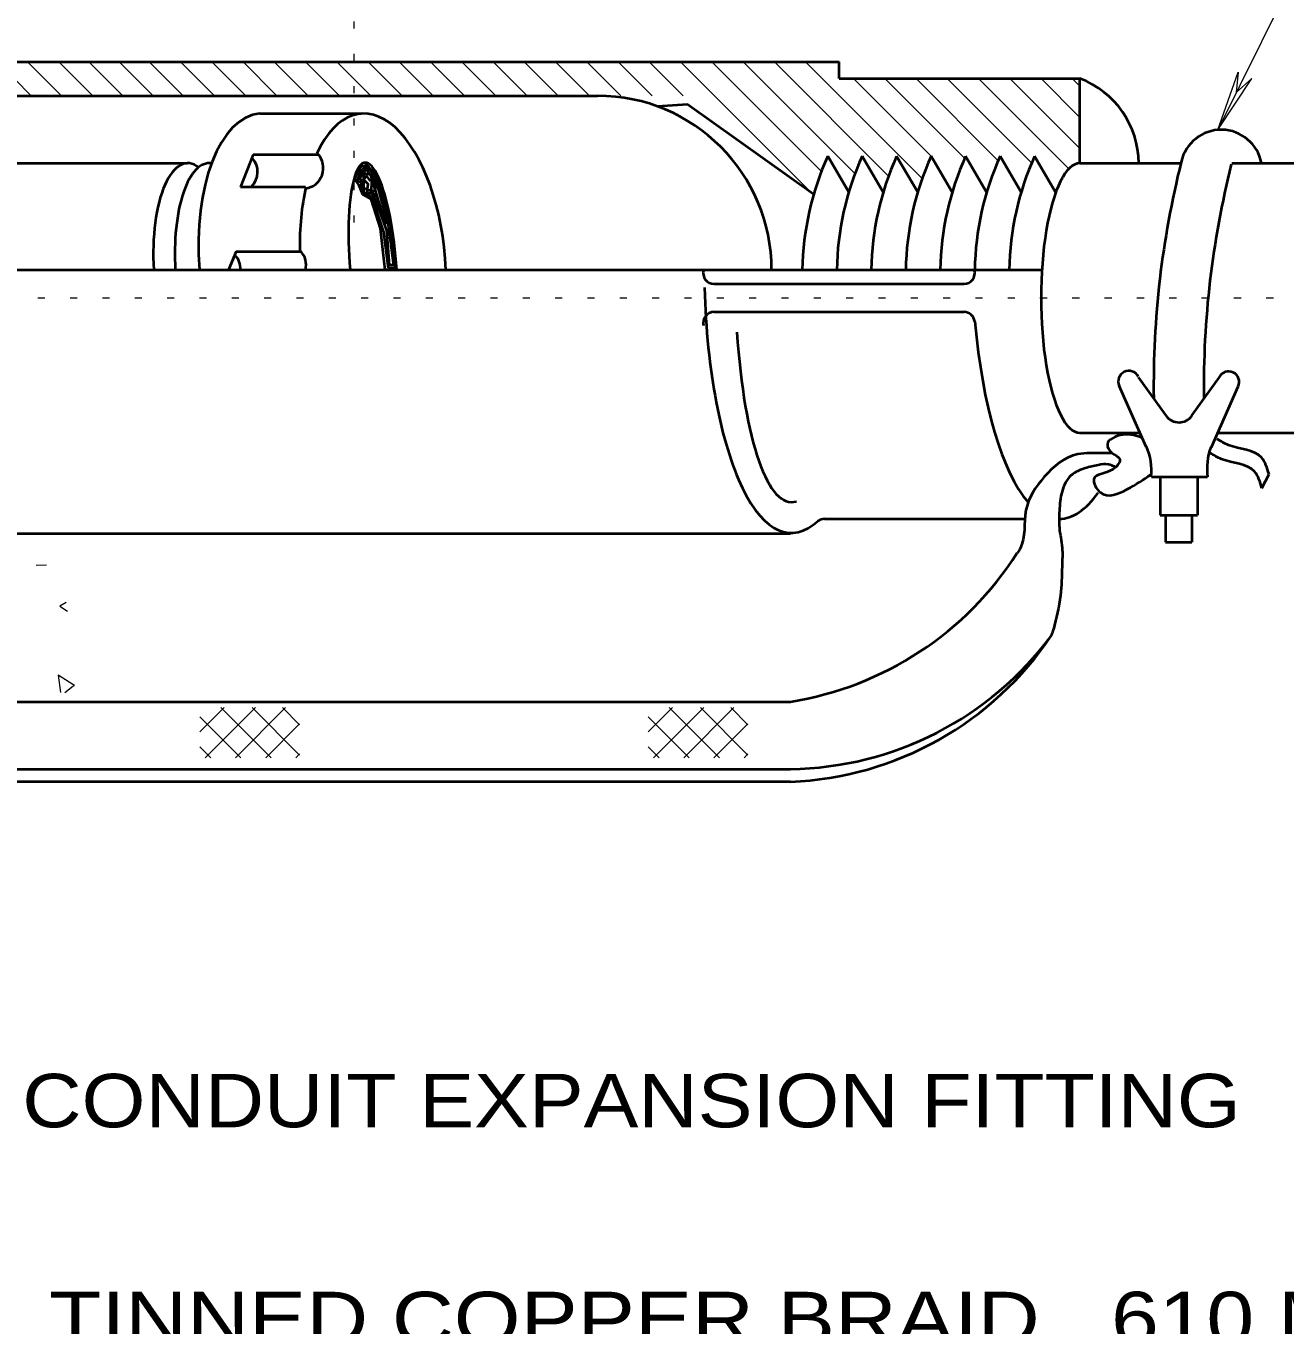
# Model space of a CAD drawing. Extents: x 312583 to 312854, y 144419 to 144597.
# Drawn here: x 312743.76 to 312761.68, y 144448.39 to 144466.88 of the extents above; entities that cross this region are included whole.
import ezdxf

# ---------------------------------------------------------------- set-up
doc = ezdxf.new("R2010")
doc.units = 0
doc.header["$LTSCALE"] = 0.3
doc.linetypes.add('DOTTED', pattern=[1.5, 0.3, -1.2])
doc.layers.add('1', color=7, linetype='Continuous', lineweight=13)

msp = doc.modelspace()

# ---------------------------------------------------------------- linework, layer by layer
at = {"layer": '1', "linetype": 'DOTTED'}
for p, q in [((312748.4299, 144464.0885), (312748.4299, 144473.2425)), ((312725.9896, 144463.0151), (312767.7882, 144463.0151))]:
    msp.add_line(p, q, dxfattribs=at)
at = {"layer": '1'}
for p, q in [((312762.9429, 144469.8845), (312760.7196, 144465.4071)), ((312743.8376, 144465.8901), (312743.3546, 144466.3731)), ((312744.2669, 144465.8901), (312743.7839, 144466.3731)), ((312744.7116, 144465.8901), (312744.2286, 144466.3731)), ((312745.1409, 144465.8901), (312744.6579, 144466.3731)), ((312745.5702, 144465.8901), (312745.0872, 144466.3731)), ((312745.9996, 144465.8901), (312745.5166, 144466.3731)), ((312746.4442, 144465.8901), (312745.9612, 144466.3731)), ((312746.8889, 144465.8901), (312746.4059, 144466.3731)), ((312747.3336, 144465.8901), (312746.8506, 144466.3731)), ((312747.7782, 144465.8901), (312747.2952, 144466.3731)), ((312748.2229, 144465.8901), (312747.7399, 144466.3731)), ((312748.6676, 144465.8901), (312748.1846, 144466.3731)), ((312749.1122, 144465.8901), (312748.6292, 144466.3731)), ((312749.5569, 144465.8901), (312749.0739, 144466.3731)), ((312750.0016, 144465.8901), (312749.5186, 144466.3731)), ((312750.4462, 144465.8901), (312749.9632, 144466.3731)), ((312750.8909, 144465.8901), (312750.4079, 144466.3731)), ((312751.3356, 144465.8901), (312750.8526, 144466.3731)), ((312751.7802, 144465.8901), (312751.2972, 144466.3731)), ((312752.2249, 144465.8901), (312751.7419, 144466.3731)), ((312752.6696, 144465.8901), (312752.1866, 144466.3731)), ((312753.1142, 144465.8901), (312752.6312, 144466.3731)), ((312754.9466, 144464.5025), (312753.0759, 144466.3731)), ((312755.0769, 144464.8168), (312753.5206, 144466.3731)), ((312755.5599, 144464.7785), (312753.9652, 144466.3731)), ((312756.0352, 144464.7478), (312754.4099, 144466.3731)), ((312756.5106, 144464.7171), (312754.8546, 144466.3731)), ((312760.7196, 144465.4071), (312761.0109, 144466.2275)), ((312761.0109, 144466.2275), (312760.9802, 144465.9361)), ((312756.6409, 144465.0315), (312755.5369, 144466.1355)), ((312757.1162, 144465.0008), (312755.9816, 144466.1355)), ((312757.5916, 144464.9701), (312756.4262, 144466.1355)), ((312758.0746, 144464.9318), (312756.8709, 144466.1355)), ((312758.5959, 144464.8551), (312757.3156, 144466.1355)), ((312758.7569, 144465.1388), (312757.7602, 144466.1355)), ((312758.7569, 144465.5835), (312758.2049, 144466.1355)), ((312758.7569, 144466.0281), (312758.6496, 144466.1355)), ((312760.7196, 144465.4071), (312761.2026, 144466.1355)), ((312761.2026, 144466.1355), (312760.9802, 144465.9361)), ((312743.9066, 144459.2125), (312744.0522, 144459.2201)), ((312746.2372, 144456.8435), (312746.5822, 144457.1885)), ((312746.3139, 144456.4755), (312747.0269, 144457.1885)), ((312747.2492, 144456.4755), (312746.5362, 144457.1885)), ((312746.7432, 144456.4755), (312747.4562, 144457.1885)), ((312747.6556, 144456.5138), (312746.9809, 144457.1885)), ((312747.6556, 144456.9431), (312747.4102, 144457.1885)), ((312752.6159, 144456.8435), (312752.9609, 144457.1885)), ((312752.6926, 144456.4755), (312753.4056, 144457.1885)), ((312753.6279, 144456.4755), (312752.9149, 144457.1885)), ((312753.1219, 144456.4755), (312753.8349, 144457.1885)), ((312754.0342, 144456.5138), (312753.3596, 144457.1885)), ((312754.0342, 144456.9431), (312753.7889, 144457.1885)), ((312746.8199, 144456.4755), (312746.2372, 144457.0581)), ((312747.1726, 144456.4755), (312747.6556, 144456.9585)), ((312753.1986, 144456.4755), (312752.6159, 144457.0581)), ((312753.5512, 144456.4755), (312754.0342, 144456.9585)), ((312746.3906, 144456.4755), (312746.2372, 144456.6288)), ((312752.7692, 144456.4755), (312752.6159, 144456.6288)), ((312747.6019, 144456.4755), (312747.6556, 144456.5291)), ((312753.9806, 144456.4755), (312754.0342, 144456.5291))]:
    msp.add_line(p, q, dxfattribs=at)
at = {"layer": '1', "lineweight": 40}
for p, q in [((312742.0589, 144466.3731), (312755.3299, 144466.3731)), ((312755.3299, 144466.1355), (312755.3299, 144466.3731)), ((312755.3299, 144466.1355), (312758.7569, 144466.1355)), ((312758.7569, 144464.9318), (312758.7569, 144466.1355)), ((312739.5212, 144465.8901), (312751.8952, 144465.8901)), ((312747.0882, 144465.6371), (312748.5296, 144465.6371)), ((312730.3596, 144464.9318), (312746.0532, 144464.9318)), ((312746.9962, 144465.0545), (312746.8122, 144464.5945)), ((312746.9962, 144465.0545), (312747.9162, 144465.0545)), ((312755.1689, 144465.0315), (312755.4679, 144464.5178)), ((312755.6596, 144465.0315), (312755.9586, 144464.5178)), ((312756.1502, 144465.0315), (312756.4492, 144464.5178)), ((312756.6409, 144465.0315), (312756.9399, 144464.5178)), ((312757.1316, 144465.0315), (312757.4306, 144464.5178)), ((312757.6222, 144465.0315), (312757.9212, 144464.5178)), ((312758.1129, 144465.0315), (312758.4119, 144464.5178)), ((312758.7569, 144464.9318), (312760.1906, 144464.9318)), ((312760.9189, 144464.9318), (312767.7882, 144464.9318)), ((312746.8122, 144464.5945), (312747.7399, 144464.5945)), ((312746.7509, 144463.6745), (312746.6436, 144463.4138)), ((312746.7509, 144463.6745), (312747.6709, 144463.6745)), ((312740.7862, 144463.4138), (312758.2202, 144463.4138)), ((312753.5512, 144463.2145), (312757.1086, 144463.2145)), ((312753.5512, 144462.8158), (312757.1086, 144462.8158)), ((312759.6999, 144460.8991), (312759.3166, 144461.7655)), ((312759.9836, 144461.3438), (312759.5926, 144461.8881)), ((312760.3516, 144461.3438), (312760.7426, 144461.8881)), ((312760.6276, 144460.8915), (312761.0109, 144461.7578)), ((312758.7569, 144461.0985), (312759.6079, 144461.0985)), ((312760.7196, 144461.0985), (312767.7882, 144461.0985)), ((312759.7766, 144460.4698), (312760.5739, 144460.4698)), ((312759.8992, 144460.4621), (312759.8992, 144459.9255)), ((312760.4282, 144460.4621), (312760.4282, 144459.9255)), ((312761.3482, 144460.3088), (312761.4479, 144460.5081)), ((312759.8992, 144459.9255), (312760.4282, 144459.9255)), ((312759.9759, 144459.9255), (312759.9759, 144459.5421)), ((312760.3516, 144459.9255), (312760.3516, 144459.5421)), ((312755.1229, 144459.8718), (312757.9749, 144459.8718)), ((312741.5989, 144459.6648), (312754.6399, 144459.6648)), ((312759.9759, 144459.5421), (312760.3516, 144459.5421)), ((312737.6889, 144457.2728), (312754.6399, 144457.2728)), ((312737.6889, 144456.3145), (312754.6399, 144456.3145)), ((312737.6889, 144456.1381), (312754.6399, 144456.1381))]:
    msp.add_line(p, q, dxfattribs=at)
for points in [[(312754.9696, 144464.4871), (312753.1756, 144465.7675), (312752.7462, 144465.7368)], [(312749.0356, 144463.4138), (312748.8746, 144463.4138), (312748.8439, 144463.6591), (312748.8056, 144464.0041), (312748.6752, 144464.4181), (312748.5526, 144464.4871), (312748.4989, 144464.6251), (312748.4376, 144464.7095), (312748.5296, 144464.8858), (312748.6062, 144464.9088), (312748.7442, 144464.7631), (312748.8286, 144464.5025), (312748.9436, 144464.0655), (312748.9819, 144463.7281), (312749.0126, 144463.4445), (312748.9206, 144463.4368), (312748.8516, 144463.9505), (312748.6982, 144464.4181), (312748.5756, 144464.4948), (312748.5296, 144464.6558), (312748.4682, 144464.6788), (312748.5526, 144464.8475), (312748.6062, 144464.8781), (312748.7212, 144464.7631), (312748.9206, 144464.0271), (312748.9896, 144463.4828), (312748.9359, 144463.4828), (312748.8976, 144463.9735), (312748.7366, 144464.4181), (312748.5679, 144464.5101), (312748.5679, 144464.6635), (312748.5066, 144464.7095), (312748.5986, 144464.8475), (312748.6676, 144464.7478), (312748.8746, 144464.0731), (312748.6906, 144464.4948), (312748.6139, 144464.5101), (312748.6292, 144464.6328), (312748.5679, 144464.6941), (312748.6062, 144464.7478), (312748.6522, 144464.6865), (312748.7212, 144464.7325), (312748.7289, 144464.5485), (312748.6752, 144464.5178), (312748.6829, 144464.6328), (312748.6906, 144464.7631), (312748.5679, 144464.7861), (312748.5602, 144464.5791), (312748.6522, 144464.5485), (312748.7442, 144464.4565)]]:
    msp.add_lwpolyline(points, dxfattribs=at)
at = {"layer": '1'}
for points in [[(312744.3359, 144458.6835), (312744.2439, 144458.6298), (312744.3512, 144458.5608)], [(312744.4509, 144457.5028), (312744.4279, 144457.5181), (312744.2209, 144457.6485), (312744.2516, 144457.4031)], [(312744.3129, 144457.4031), (312744.4279, 144457.4951), (312744.4509, 144457.5028)]]:
    msp.add_lwpolyline(points, dxfattribs=at)
at = {"layer": '1', "lineweight": 40}
for centre, radius, start, end in [((312758.3016, 144464.9264), 1.292, 0.24072, 69.36647), ((312751.8952, 144463.4138), 2.4763, 0, 90), ((312760.7679, 144464.8246), 0.5827, 10.59906, 167.86288), ((312746.7632, 144464.8091), 0.2945, 313.20051, 42.47617), ((312747.6985, 144464.8628), 0.2945, 277.96991, 42.47617), ((312758.89, 144463.3522), 4.0824, 155.71072, 179.13516), ((312759.3806, 144463.3522), 4.0824, 155.71072, 179.13516), ((312759.8713, 144463.3522), 4.0824, 155.71072, 179.13516), ((312760.362, 144463.3522), 4.0824, 155.71072, 179.13516), ((312760.8526, 144463.3522), 4.0824, 155.71072, 179.13516), ((312761.3433, 144463.3522), 4.0824, 155.71072, 179.13516), ((312761.834, 144463.3522), 4.0824, 155.71072, 179.13516), ((312772.8425, 144461.7755), 13.0359, 165.91883, 180.82259), ((312773.5555, 144461.7449), 13.0359, 165.91883, 180.72864), ((312746.5179, 144463.4291), 0.2945, 357.01533, 42.47617), ((312747.4532, 144463.4828), 0.2945, 346.44908, 42.47617), ((312753.5512, 144463.3678), 0.1533, 165.25644, 270), ((312757.1086, 144463.3678), 0.1533, 270, 14.74356), ((312753.5512, 144462.6625), 0.1533, 90, 194.74356), ((312757.1086, 144462.6625), 0.1533, 6.34019, 90), ((312759.4546, 144461.8268), 0.151, 27.89727, 203.96249), ((312760.8729, 144461.8191), 0.151, 336.03751, 152.10273), ((312760.1676, 144461.4743), 0.23, 215.31121, 324.68879), ((312758.9332, 144460.5541), 0.8438, 354.28941, 24.22774), ((312761.4096, 144460.5925), 0.8438, 159.26129, 188.35075), ((312755.1229, 144459.7185), 0.1533, 90, 126.8699), ((312753.9026, 144461.915), 4.7005, 279.02485, 327.49763), ((312757.8714, 144458.4113), 0.5218, 338.90205, 347.69946), ((312754.5771, 144461.0146), 4.7005, 270.76554, 323.52738), ((312754.4467, 144460.8292), 4.7005, 272.35877, 326.33013)]:
    msp.add_arc(centre, radius, start, end, dxfattribs=at)
for centre, major_axis, ratio, start_param, end_param in [((312747.2581, 144463.4954), (-0.1699, 2.1418), 0.480227, 6.2831853, 7.8539816), ((312748.6994, 144463.4954), (-0.1699, 2.1418), 0.480227, 4.6363619, 6.991541), ((312746.1264, 144463.4798), (-0.0732, 1.452), 0.377783, 5.9815228, 7.8802166), ((312746.4331, 144463.4798), (-0.0732, 1.452), 0.377783, 6.2064649, 7.8802166), ((312748.6994, 144463.4954), (-0.1145, 1.4434), 0.228731, 4.6374354, 7.8923792), ((312758.7569, 144463.0151), (0, 1.9167), 0.288, 6.2831853, 9.424778), ((312748.6994, 144463.4954), (-0.1699, 2.1418), 0.480227, 0.9927836, 1.4420674), ((312754.7394, 144463.8112), (-0.0995, -4.1388), 0.320432, 4.8776978, 6.5794282), ((312758.5498, 144464.0106), (-0.0995, -4.1388), 0.320432, 5.047256, 5.9492776), ((312754.7394, 144463.8112), (-0.089, -3.7001), 0.239872, 5.0717848, 6.3660556), ((312758.5498, 144464.0106), (-0.0995, -4.1388), 0.320432, 0.0115571, 0.4347576)]:
    msp.add_ellipse(centre, major_axis=major_axis, ratio=ratio, start_param=start_param, end_param=end_param, dxfattribs=at)
for points in [[(312759.6539, 144461.0218), (312759.3702, 144461.0678), (312759.1479, 144460.9298), (312759.2092, 144460.8148), (312759.3242, 144460.7228), (312759.2246, 144460.5771), (312758.9562, 144460.4391), (312759.0482, 144460.2475), (312759.4316, 144460.2935), (312759.7612, 144460.5005)], [(312761.4479, 144460.5081), (312761.3406, 144460.7458), (312760.8729, 144460.9221), (312760.7119, 144461.0065)], [(312759.2169, 144460.8071), (312758.9026, 144460.8071), (312758.7262, 144460.7918), (312758.2509, 144460.4698), (312757.9902, 144459.9945), (312757.9059, 144459.4501), (312757.8676, 144459.3888)], [(312759.2552, 144460.6155), (312759.1632, 144460.6461), (312759.0176, 144460.6385), (312758.8336, 144460.5925), (312758.6342, 144460.4928), (312758.5039, 144460.2628), (312758.4656, 144459.9868), (312758.4656, 144459.7491), (312758.5039, 144459.4655), (312758.5039, 144459.1971), (312758.4809, 144458.7831), (312758.3812, 144458.3001)], [(312761.3482, 144460.3088), (312761.2409, 144460.5465), (312760.7732, 144460.7228), (312760.6122, 144460.8071)]]:
    msp.add_spline(points, degree=3, dxfattribs=at)

# ---------------------------------------------------------------- texts
at = {"layer": '1'}
for s, width, p in [('CONDUIT EXPANSION FITTING', 1.15, (312743.709, 144451.219)), ('TINNED COPPER BRAID,  610 MM LG.', 1.2, (312744.0903, 144448.1198))]:
    msp.add_text(s, height=0.76, dxfattribs=dict(at, width=width)).set_placement(p)

doc.saveas('drawing.dxf')
